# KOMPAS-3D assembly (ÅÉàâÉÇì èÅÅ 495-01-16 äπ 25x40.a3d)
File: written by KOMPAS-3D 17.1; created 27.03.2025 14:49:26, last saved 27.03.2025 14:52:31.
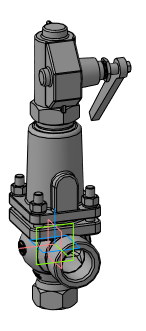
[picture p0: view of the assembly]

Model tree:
1. Операция без истории:1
